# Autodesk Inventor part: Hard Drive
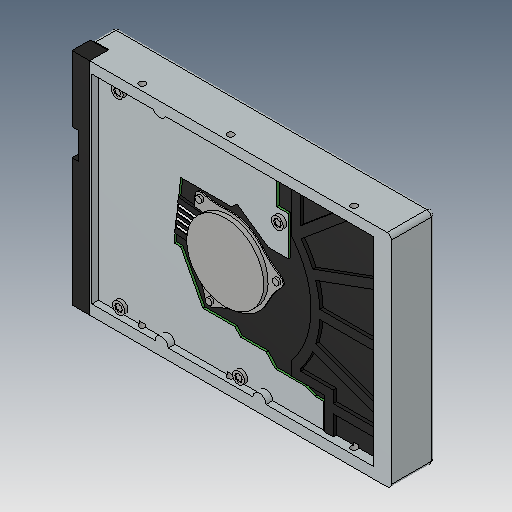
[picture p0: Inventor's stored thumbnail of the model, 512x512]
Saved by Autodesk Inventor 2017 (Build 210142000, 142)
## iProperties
Created: 2005-12
Part Number: Hard Drive
Material: Generic
Document SubType Name: Modeling
Designer: DanielSeverino
Density: 1 g/cm^3
Appearance: Default
Author: DanielSeverino
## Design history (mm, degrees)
feature "Solid1"
body "Solid2"
